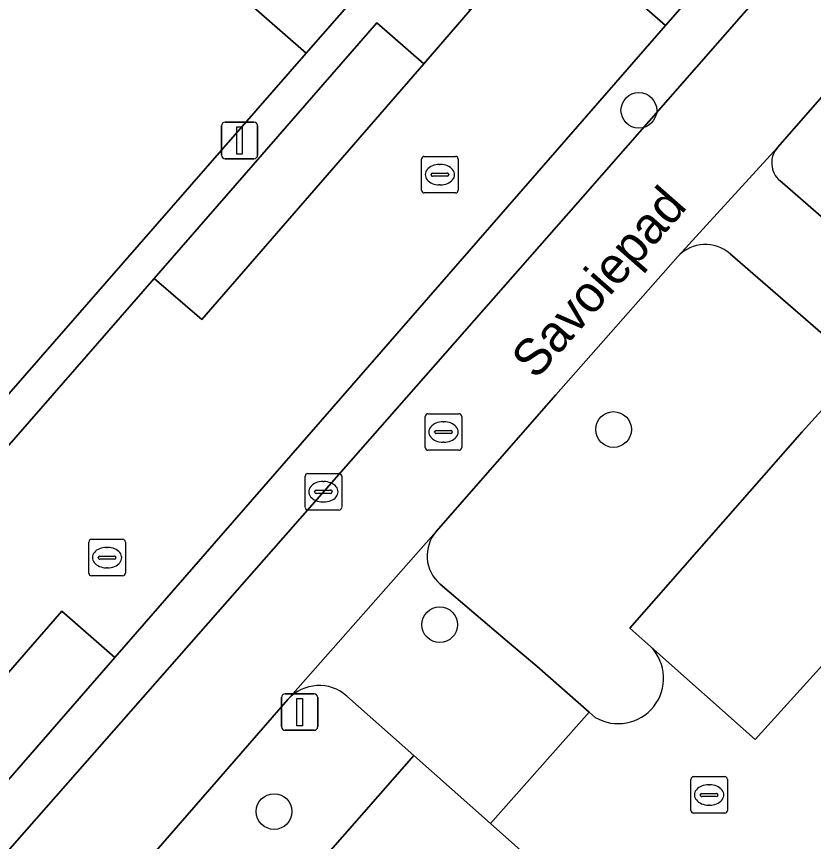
# Model space of a CAD drawing. Extents: x 158472 to 159562, y 388525 to 389606.
# Drawn here: x 158911.21 to 158933.03, y 388825.82 to 388848.41 of the extents above; entities that cross this region are included whole.
import ezdxf

# ---------------------------------------------------------------- set-up
doc = ezdxf.new("R2010")
doc.units = 0
for name, color, linetype in [('IMGEO_Berm_groen', 7, 'Continuous'), ('IMGEO_Boom', 7, 'Continuous'), ('IMGEO_Erf', 7, 'Continuous'), ('IMGEO_Fietspad_gesloten', 7, 'Continuous'), ('IMGEO_Groenvoorziening', 7, 'Continuous'), ('IMGEO_Haag', 7, 'Continuous'), ('IMGEO_Kolk', 7, 'Continuous'), ('IMGEO_Lichtmast', 7, 'Continuous'), ('IMGEO_Muur', 7, 'Continuous'), ('IMGEO_Openbare_ruimte_label', 7, 'Continuous'), ('IMGEO_Pand', 7, 'Continuous'), ('IMGEO_Parkeervlak_open', 7, 'Continuous'), ('IMGEO_Rijbaan_lokaal_open', 7, 'Continuous'), ('IMGEO_Rioolput', 7, 'Continuous'), ('IMGEO_Voetpad_open', 7, 'Continuous')]:
    doc.layers.add(name, color=color, linetype=linetype)

msp = doc.modelspace()

# ---------------------------------------------------------------- linework, layer by layer
at = {"layer": 'IMGEO_Berm_groen'}
for points in [[(158954.488, 388865.021), (158951.767, 388867.379), (158941.937, 388856.138), (158932.045, 388844.827)], [(158932.107, 388843.92), (158934.223, 388842.084), (158954.488, 388865.021)]]:
    msp.add_lwpolyline(points, dxfattribs=at)
msp.add_arc((158932.526, 388844.404), 0.64, 138.6679, 229.1531, dxfattribs=at)
at = {"layer": 'IMGEO_Boom'}
for centre in [(158928.248, 388845.845), (158927.555, 388837.105), (158922.795, 388831.76), (158918.26, 388826.644)]:
    msp.add_circle(centre, 0.489, dxfattribs=at)
at = {"layer": 'IMGEO_Erf'}
for points in [[(158864.451, 388784.733), (158911.812, 388839.017), (158919.136, 388847.412), (158916.764, 388849.489)], [(158948.022, 388803.56), (158944.187, 388806.882), (158938.98, 388811.457), (158935.123, 388814.752), (158932.03, 388817.43), (158932.924, 388818.579), (158930.914, 388820.395), (158927.08, 388823.739), (158924.182, 388826.315), (158922.086, 388828.178), (158895.45, 388797.816)]]:
    msp.add_lwpolyline(points, dxfattribs=at)
at = {"layer": 'IMGEO_Fietspad_gesloten'}
msp.add_lwpolyline([(158939.547, 388858.13), (158926.586, 388843.327), (158908.631, 388822.912), (158891.98, 388803.837), (158886.534, 388797.524), (158886.262, 388797.803), (158884.323, 388795.61), (158883.327, 388794.483), (158872.522, 388782.263), (158876.002, 388779.209), (158877.157, 388780.522), (158889.917, 388795.054), (158889.244, 388795.75), (158891.577, 388798.482), (158892.838, 388800.078), (158918.64, 388829.712), (158922.701, 388834.313), (158925.978, 388838.056), (158929.322, 388841.85), (158932.045, 388844.827), (158941.937, 388856.138)], dxfattribs=at)
at = {"layer": 'IMGEO_Groenvoorziening'}
msp.add_lwpolyline([(158908.631, 388822.912), (158926.586, 388843.327), (158939.547, 388858.13), (158938.627, 388858.934), (158938.477, 388859.066), (158930.791, 388850.245), (158928.977, 388848.164), (158913.904, 388830.865), (158908.033, 388824.128), (158902.113, 388817.333), (158896.228, 388810.579), (158890.332, 388803.813), (158884.464, 388797.078), (158883.671, 388796.168), (158883.813, 388796.047), (158884.323, 388795.61), (158886.262, 388797.803), (158886.534, 388797.524), (158891.98, 388803.837)], close=True, dxfattribs=at)
for points in [[(158929.322, 388841.85), (158925.978, 388838.056), (158922.701, 388834.313)], [(158932.722, 388837.039), (158934.325, 388838.808), (158930.748, 388841.919)], [(158928.578, 388831.153), (158928.005, 388831.661), (158932.722, 388837.039)], [(158922.807, 388832.874), (158924.656, 388831.302), (158925.453, 388830.624), (158926.892, 388829.365), (158927.054, 388829.223)], [(158918.64, 388829.712), (158892.838, 388800.078), (158895.45, 388797.816), (158922.086, 388828.178), (158920.255, 388829.805)]]:
    msp.add_lwpolyline(points, dxfattribs=at)
for centre, radius, start, end in [((158930.071, 388841.141), 1.032, 48.9865, 136.554), ((158923.463, 388833.646), 1.013, 138.8061, 229.6198), ((158927.684, 388830.292), 1.241, 239.488, 43.9201), ((158919.494, 388828.948), 1.146, 48.4121, 138.1794)]:
    msp.add_arc(centre, radius, start, end, dxfattribs=at)
at = {"layer": 'IMGEO_Haag'}
msp.add_lwpolyline([(158926.586, 388843.327), (158939.547, 388858.13), (158938.627, 388858.934), (158938.477, 388859.066), (158930.791, 388850.245), (158928.977, 388848.164), (158913.904, 388830.865), (158908.033, 388824.128), (158902.113, 388817.333), (158896.228, 388810.579), (158890.332, 388803.813), (158884.464, 388797.078), (158883.671, 388796.168), (158883.813, 388796.047), (158884.323, 388795.61), (158886.262, 388797.803), (158886.534, 388797.524), (158891.98, 388803.837), (158908.631, 388822.912)], close=True, dxfattribs=at)
msp.add_lwpolyline([(158918.64, 388829.712), (158892.838, 388800.078), (158895.45, 388797.816), (158922.086, 388828.178), (158920.255, 388829.805)], dxfattribs=at)
msp.add_arc((158919.494, 388828.948), 1.146, 48.4121, 138.1794, dxfattribs=at)
at = {"layer": 'IMGEO_Kolk'}
for p, q in [((158922.299, 388843.658), (158922.299, 388844.51)), ((158922.374, 388844.584), (158923.226, 388844.584)), ((158923.3, 388844.51), (158923.3, 388843.658)), ((158922.787, 388844.364), (158922.812, 388844.364)), ((158922.558, 388844.078), (158922.558, 388844.09)), ((158922.996, 388844.041), (158922.598, 388844.041)), ((158922.601, 388844.127), (158922.999, 388844.127)), ((158923.042, 388844.09), (158923.042, 388844.078)), ((158922.81, 388843.804), (158922.785, 388843.804)), ((158923.226, 388843.584), (158922.374, 388843.584)), ((158919.185, 388835.9), (158920.037, 388835.9)), ((158919.11, 388834.974), (158919.11, 388835.826)), ((158919.598, 388835.68), (158919.623, 388835.68)), ((158920.111, 388835.826), (158920.111, 388834.974)), ((158919.369, 388835.394), (158919.369, 388835.406)), ((158919.412, 388835.443), (158919.81, 388835.443)), ((158919.853, 388835.406), (158919.853, 388835.394)), ((158919.807, 388835.357), (158919.409, 388835.357)), ((158919.621, 388835.12), (158919.596, 388835.12)), ((158920.037, 388834.9), (158919.185, 388834.9)), ((158913.262, 388834.098), (158914.114, 388834.098)), ((158913.187, 388833.172), (158913.187, 388834.024)), ((158913.675, 388833.878), (158913.7, 388833.878)), ((158914.188, 388834.024), (158914.188, 388833.172)), ((158913.446, 388833.592), (158913.446, 388833.604)), ((158913.489, 388833.641), (158913.887, 388833.641)), ((158913.93, 388833.604), (158913.93, 388833.592)), ((158913.884, 388833.555), (158913.486, 388833.555)), ((158913.698, 388833.318), (158913.673, 388833.318)), ((158914.114, 388833.098), (158913.262, 388833.098)), ((158929.672, 388826.673), (158929.672, 388827.525)), ((158929.747, 388827.599), (158930.599, 388827.599)), ((158930.673, 388827.525), (158930.673, 388826.673)), ((158930.16, 388827.379), (158930.185, 388827.379)), ((158929.931, 388827.093), (158929.931, 388827.105)), ((158930.369, 388827.056), (158929.971, 388827.056)), ((158929.974, 388827.142), (158930.372, 388827.142)), ((158930.415, 388827.105), (158930.415, 388827.093)), ((158930.183, 388826.819), (158930.158, 388826.819)), ((158930.599, 388826.599), (158929.747, 388826.599))]:
    msp.add_line(p, q, dxfattribs=at)
for points in [[(158922.299, 388843.658), (158922.299, 388844.51)], [(158922.374, 388844.584), (158923.226, 388844.584)], [(158923.3, 388844.51), (158923.3, 388843.658)], [(158923.226, 388843.584), (158922.374, 388843.584)], [(158919.185, 388835.9), (158920.037, 388835.9)], [(158919.11, 388834.974), (158919.11, 388835.826)], [(158920.111, 388835.826), (158920.111, 388834.974)], [(158920.037, 388834.9), (158919.185, 388834.9)], [(158913.262, 388834.098), (158914.114, 388834.098)], [(158913.187, 388833.172), (158913.187, 388834.024)], [(158914.188, 388834.024), (158914.188, 388833.172)], [(158914.114, 388833.098), (158913.262, 388833.098)], [(158929.672, 388826.673), (158929.672, 388827.525)], [(158929.747, 388827.599), (158930.599, 388827.599)], [(158930.673, 388827.525), (158930.673, 388826.673)], [(158930.599, 388826.599), (158929.747, 388826.599)]]:
    msp.add_lwpolyline(points, dxfattribs=at)
for centre, radius, start, end in [((158922.376, 388844.508), 0.0765, 91.552, 178.448), ((158922.376, 388844.508), 0.0765, 91.552, 178.448), ((158923.224, 388844.508), 0.0765, 1.552, 88.448), ((158923.224, 388844.508), 0.0765, 1.552, 88.448), ((158922.598, 388844.087), 0.0403, 85.8775, 175.7526), ((158922.595, 388844.077), 0.0366, 178.938, 274.7102), ((158922.999, 388844.084), 0.043, 264.8664, 352.4533), ((158923.003, 388844.089), 0.0386, 1.7309, 96.639), ((158922.376, 388843.66), 0.0765, 181.552, 268.448), ((158922.376, 388843.66), 0.0765, 181.552, 268.448), ((158923.224, 388843.66), 0.0765, 271.552, 358.448), ((158923.224, 388843.66), 0.0765, 271.552, 358.448), ((158919.187, 388835.824), 0.0765, 91.552, 178.448), ((158919.187, 388835.824), 0.0765, 91.552, 178.448), ((158920.035, 388835.824), 0.0765, 1.552, 88.448), ((158920.035, 388835.824), 0.0765, 1.552, 88.448), ((158919.409, 388835.403), 0.0403, 85.8775, 175.7526), ((158919.406, 388835.393), 0.0366, 178.938, 274.7102), ((158919.81, 388835.4), 0.043, 264.8664, 352.4533), ((158919.814, 388835.405), 0.0386, 1.7309, 96.639), ((158919.187, 388834.976), 0.0765, 181.552, 268.448), ((158919.187, 388834.976), 0.0765, 181.552, 268.448), ((158920.035, 388834.976), 0.0765, 271.552, 358.448), ((158920.035, 388834.976), 0.0765, 271.552, 358.448), ((158913.264, 388834.022), 0.0765, 91.552, 178.448), ((158913.264, 388834.022), 0.0765, 91.552, 178.448), ((158914.112, 388834.022), 0.0765, 1.552, 88.448), ((158914.112, 388834.022), 0.0765, 1.552, 88.448), ((158913.486, 388833.601), 0.0403, 85.8775, 175.7526), ((158913.483, 388833.591), 0.0366, 178.938, 274.7102), ((158913.887, 388833.598), 0.043, 264.8664, 352.4533), ((158913.891, 388833.603), 0.0386, 1.7309, 96.639), ((158913.264, 388833.174), 0.0765, 181.552, 268.448), ((158913.264, 388833.174), 0.0765, 181.552, 268.448), ((158914.112, 388833.174), 0.0765, 271.552, 358.448), ((158914.112, 388833.174), 0.0765, 271.552, 358.448), ((158929.749, 388827.523), 0.0765, 91.552, 178.448), ((158929.749, 388827.523), 0.0765, 91.552, 178.448), ((158930.597, 388827.523), 0.0765, 1.552, 88.448), ((158930.597, 388827.523), 0.0765, 1.552, 88.448), ((158929.971, 388827.102), 0.0403, 85.8775, 175.7526), ((158929.968, 388827.092), 0.0366, 178.938, 274.7102), ((158930.372, 388827.099), 0.043, 264.8664, 352.4533), ((158930.376, 388827.104), 0.0386, 1.7309, 96.639), ((158929.749, 388826.675), 0.0765, 181.552, 268.448), ((158929.749, 388826.675), 0.0765, 181.552, 268.448), ((158930.597, 388826.675), 0.0765, 271.552, 358.448), ((158930.597, 388826.675), 0.0765, 271.552, 358.448)]:
    msp.add_arc(centre, radius, start, end, dxfattribs=at)
for centre, major_axis, ratio, start_param, end_param in [((158922.786, 388844.084), (-0.387, 0.002), 0.722429, 4.712389, 7.853982), ((158922.811, 388844.084), (-0.39, 0.002), 0.717154, 1.570796, 4.712389), ((158919.597, 388835.4), (-0.387, 0.002), 0.722429, 4.712389, 7.853982), ((158919.622, 388835.4), (-0.39, 0.002), 0.717154, 1.570796, 4.712389), ((158913.674, 388833.598), (-0.387, 0.002), 0.722429, 4.712389, 7.853982), ((158913.699, 388833.598), (-0.39, 0.002), 0.717154, 1.570796, 4.712389), ((158930.159, 388827.099), (-0.387, 0.002), 0.722429, 4.712389, 7.853982), ((158930.184, 388827.099), (-0.39, 0.002), 0.717154, 1.570796, 4.712389)]:
    msp.add_ellipse(centre, major_axis=major_axis, ratio=ratio, start_param=start_param, end_param=end_param, dxfattribs=at)
at = {"layer": 'IMGEO_Lichtmast'}
for p, q in [((158916.82, 388844.621), (158916.82, 388845.421)), ((158916.82, 388845.421), (158916.82, 388844.621)), ((158916.92, 388845.521), (158917.71, 388845.521)), ((158917.71, 388845.521), (158916.92, 388845.521)), ((158917.81, 388845.421), (158917.81, 388844.621)), ((158917.81, 388844.621), (158917.81, 388845.421)), ((158917.71, 388844.521), (158916.92, 388844.521)), ((158916.92, 388844.521), (158917.71, 388844.521)), ((158918.465, 388828.968), (158918.465, 388829.768)), ((158918.465, 388829.768), (158918.465, 388828.968)), ((158918.565, 388829.868), (158919.355, 388829.868)), ((158919.355, 388829.868), (158918.565, 388829.868)), ((158919.455, 388829.768), (158919.455, 388828.968)), ((158919.455, 388828.968), (158919.455, 388829.768)), ((158919.355, 388828.868), (158918.565, 388828.868)), ((158918.565, 388828.868), (158919.355, 388828.868))]:
    msp.add_line(p, q, dxfattribs=at)
for points in [[(158917.24, 388845.396), (158917.39, 388845.396), (158917.39, 388844.646), (158917.24, 388844.646), (158917.24, 388845.396)], [(158918.885, 388829.743), (158919.035, 388829.743), (158919.035, 388828.993), (158918.885, 388828.993), (158918.885, 388829.743)]]:
    msp.add_lwpolyline(points, dxfattribs=at)
for centre, start, end in [((158916.92, 388845.421), 90, 180), ((158916.92, 388845.421), 90, 180), ((158917.71, 388845.421), 0, 90), ((158917.71, 388845.421), 360, 90), ((158916.92, 388844.621), 180, 270), ((158916.92, 388844.621), 180, 270), ((158917.71, 388844.621), 270, 0), ((158917.71, 388844.621), 270, 0), ((158918.565, 388829.768), 90, 180), ((158918.565, 388829.768), 90, 180), ((158919.355, 388829.768), 0, 90), ((158919.355, 388829.768), 360, 90), ((158918.565, 388828.968), 180, 270), ((158918.565, 388828.968), 180, 270), ((158919.355, 388828.968), 270, 0), ((158919.355, 388828.968), 270, 0)]:
    msp.add_arc(centre, 0.1, start, end, dxfattribs=at)
at = {"layer": 'IMGEO_Muur'}
msp.add_lwpolyline([(158919.136, 388847.412), (158911.812, 388839.017)], dxfattribs=at)
at = {"layer": 'IMGEO_Pand'}
msp.add_lwpolyline([(158914.149, 388855.764), (158918.739, 388851.746), (158916.764, 388849.489), (158919.136, 388847.412), (158923.245, 388852.106), (158920.938, 388854.126), (158924.865, 388858.613), (158920.205, 388862.692)], close=True, dxfattribs=at)
at = {"layer": 'IMGEO_Parkeervlak_open'}
for points in [[(158914.973, 388841.243), (158916.285, 388840.115), (158922.361, 388847.122), (158921.074, 388848.243)], [(158937.853, 388835.702), (158934.325, 388838.808), (158932.722, 388837.039), (158928.005, 388831.661), (158928.578, 388831.153), (158931.435, 388828.62)], [(158913.904, 388830.865), (158912.453, 388832.13), (158906.584, 388825.391), (158908.033, 388824.128)]]:
    msp.add_lwpolyline(points, close=True, dxfattribs=at)
at = {"layer": 'IMGEO_Rijbaan_lokaal_open'}
msp.add_lwpolyline([(158925.739, 388851.017), (158928.977, 388848.164), (158930.791, 388850.245), (158927.537, 388853.09)], close=True, dxfattribs=at)
for points in [[(158896.228, 388810.579), (158894.776, 388811.844), (158900.662, 388818.597), (158902.113, 388817.333), (158908.033, 388824.128), (158906.584, 388825.391), (158912.453, 388832.13), (158913.904, 388830.865), (158928.977, 388848.164), (158925.739, 388851.017), (158923.631, 388848.586), (158922.361, 388847.122), (158916.285, 388840.115), (158914.973, 388841.243), (158865.195, 388784.143)], [(158942.646, 388831.471), (158937.853, 388835.702), (158931.435, 388828.62), (158928.578, 388831.153)], [(158927.054, 388829.223), (158926.892, 388829.365), (158924.182, 388826.315), (158927.08, 388823.739), (158928.05, 388824.862), (158959.175, 388797.838), (158965.788, 388805.265), (158969.246, 388809.149), (158962.92, 388814.631), (158959.478, 388810.733), (158956.854, 388807.76), (158955.341, 388809.01), (158939.082, 388823.238), (158937.005, 388824.955), (158942.646, 388831.471)]]:
    msp.add_lwpolyline(points, dxfattribs=at)
msp.add_arc((158927.684, 388830.292), 1.241, 239.488, 43.9201, dxfattribs=at)
at = {"layer": 'IMGEO_Rioolput'}
for p, q in [((158922.398, 388836.611), (158922.398, 388837.463)), ((158922.473, 388837.537), (158923.325, 388837.537)), ((158923.399, 388837.463), (158923.399, 388836.611)), ((158922.886, 388837.317), (158922.911, 388837.317)), ((158922.657, 388837.031), (158922.657, 388837.043)), ((158923.095, 388836.994), (158922.697, 388836.994)), ((158922.7, 388837.08), (158923.098, 388837.08)), ((158923.141, 388837.043), (158923.141, 388837.031)), ((158922.909, 388836.757), (158922.884, 388836.757)), ((158923.325, 388836.537), (158922.473, 388836.537))]:
    msp.add_line(p, q, dxfattribs=at)
for points in [[(158922.398, 388836.611), (158922.398, 388837.463)], [(158922.473, 388837.537), (158923.325, 388837.537)], [(158923.399, 388837.463), (158923.399, 388836.611)], [(158923.325, 388836.537), (158922.473, 388836.537)]]:
    msp.add_lwpolyline(points, dxfattribs=at)
for centre, radius, start, end in [((158922.475, 388837.461), 0.0765, 91.552, 178.448), ((158922.475, 388837.461), 0.0765, 91.552, 178.448), ((158923.323, 388837.461), 0.0765, 1.552, 88.448), ((158923.323, 388837.461), 0.0765, 1.552, 88.448), ((158922.697, 388837.04), 0.0403, 85.8775, 175.7526), ((158922.694, 388837.03), 0.0366, 178.938, 274.7102), ((158923.098, 388837.037), 0.043, 264.8664, 352.4533), ((158923.102, 388837.042), 0.0386, 1.7309, 96.639), ((158922.475, 388836.613), 0.0765, 181.552, 268.448), ((158922.475, 388836.613), 0.0765, 181.552, 268.448), ((158923.323, 388836.613), 0.0765, 271.552, 358.448), ((158923.323, 388836.613), 0.0765, 271.552, 358.448)]:
    msp.add_arc(centre, radius, start, end, dxfattribs=at)
for centre, major_axis, ratio, start_param, end_param in [((158922.885, 388837.037), (-0.387, 0.002), 0.722429, 4.712389, 7.853982), ((158922.91, 388837.037), (-0.39, 0.002), 0.717154, 1.570796, 4.712389)]:
    msp.add_ellipse(centre, major_axis=major_axis, ratio=ratio, start_param=start_param, end_param=end_param, dxfattribs=at)
at = {"layer": 'IMGEO_Voetpad_open'}
for points in [[(158932.289, 388858.569), (158930.295, 388860.304), (158929.092, 388858.899), (158923.245, 388852.106), (158919.136, 388847.412), (158911.812, 388839.017), (158864.451, 388784.733)], [(158865.195, 388784.143), (158914.973, 388841.243), (158921.074, 388848.243), (158922.361, 388847.122), (158923.631, 388848.586), (158922.347, 388849.704), (158928.27, 388856.495), (158929.535, 388855.393), (158932.289, 388858.569)], [(158932.045, 388844.827), (158929.322, 388841.85)], [(158964.083, 388816.165), (158962.949, 388817.149), (158935.951, 388840.584), (158934.223, 388842.084), (158932.107, 388843.92)], [(158930.748, 388841.919), (158934.325, 388838.808), (158937.853, 388835.702), (158942.646, 388831.471), (158937.005, 388824.955), (158939.082, 388823.238), (158942.175, 388826.678), (158958.574, 388812.427), (158955.341, 388809.01), (158956.854, 388807.76), (158959.478, 388810.733), (158962.92, 388814.631), (158969.246, 388809.149), (158965.788, 388805.265), (158969.296, 388802.14), (158970.588, 388801.233), (158972.066, 388799.994), (158973.085, 388801.192), (158975.512, 388804.045), (158976.586, 388805.308), (158975.565, 388806.198), (158975.043, 388806.651), (158969.67, 388811.315), (158964.083, 388816.165)], [(158922.701, 388834.313), (158918.64, 388829.712)], [(158925.453, 388830.624), (158924.656, 388831.302), (158922.807, 388832.874)], [(158920.255, 388829.805), (158922.086, 388828.178), (158924.182, 388826.315), (158926.892, 388829.365), (158925.453, 388830.624)]]:
    msp.add_lwpolyline(points, dxfattribs=at)
for centre, radius, start, end in [((158932.526, 388844.404), 0.64, 138.6679, 229.1531), ((158930.071, 388841.141), 1.032, 48.9865, 136.554), ((158923.463, 388833.646), 1.013, 138.8061, 229.6198), ((158919.494, 388828.948), 1.146, 48.4121, 138.1794)]:
    msp.add_arc(centre, radius, start, end, dxfattribs=at)

# ---------------------------------------------------------------- texts
at = {"layer": 'IMGEO_Openbare_ruimte_label'}
msp.add_text('Savoiepad', height=1, rotation=48.6901, dxfattribs=at).set_placement((158925.431, 388838.446))

doc.saveas('drawing.dxf')
